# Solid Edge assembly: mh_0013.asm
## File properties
Title: grip_r_unit
Author: edge
Template: normal.asm
Last saved by: edge
Revision: 32
Application: Solid Edge
文書内容のタイプ: 1
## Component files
mh_0019.par
mh_0016.par
mh_0015.par
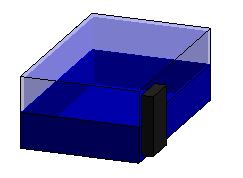
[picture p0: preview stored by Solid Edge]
